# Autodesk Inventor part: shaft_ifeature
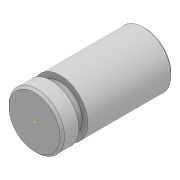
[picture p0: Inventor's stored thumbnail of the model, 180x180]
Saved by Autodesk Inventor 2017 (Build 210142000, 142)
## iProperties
Created: 2016-06
Part Number: shaft_ifeature
Material: Generic
Document SubType Name: Modeling
Designer: CADCIM
Density: 1 g/cm^3
Appearance: Default
Author: CADCIM
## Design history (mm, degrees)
sketch "Sketch1"
  geometry: 1 further point
sketch "Sketch2"
  geometry: L1 (0, 100)-(-25, 100); L2 (-25, 100)-(-25, 23); L3 (-25, 23)-(-20, 23); L4 (-20, 23)-(-20, 15); L5 (-20, 15)-(-25, 15); L6 (-25, 15)-(-25, 0); L7 (-25, 0)-(0, 0); L8 (0, 0)-(0, 100)
  constraints: 16 end point, 6 perpendicular, 2 point on line, 1 horizontal
  dimensions: "d0" = 50 diameter of L6.end L8; "d1" = 40 diameter of L4.end L8; "d2" = 8 distance of L3.end L4.end; "d3" = 100 distance of L6.end L1.end; "d4" = 15 distance of L5.end L6.end
revolve "Revolution1" sketch "Sketch2" stored, may be unused: angle "d5" = 90 deg
chamfer "Chamfer1" distance "d6" = 2; stored, may be unused: second distance "d7" = 2, angle "d8" = 45 deg
chamfer "Chamfer2" distance "d9" = 2; stored, may be unused: second distance "d10" = 2, angle "d11" = 45 deg
body "Solid1"
